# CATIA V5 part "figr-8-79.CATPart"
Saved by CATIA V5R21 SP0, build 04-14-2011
Part number: Part1
Bounding box of the stored display mesh (mm): x -35 to 35, y -116.369 to 116.369, z 0 to 117.647
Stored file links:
  D:\CATIA V5R21 E-RESOURCES\CATIA-V5R21\catia-v5r21-prt\c08-catia-v5r20-prt\c08-catia-v5r21-figr-8-79.CATPart
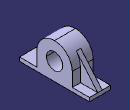
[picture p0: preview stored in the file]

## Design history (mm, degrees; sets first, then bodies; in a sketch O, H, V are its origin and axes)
Body1 (main body)
  Sketch1 on yz-plane, origin (0, 0, 0), H (0, 1, 0), V (0, 0, 1)
    line L1 (0, 0) -> (116.3687, 0)
    point P1 (116.3687, 0)
    line L2 (116.3687, 0) -> (116.3687, 12.5279)
    point P2 (116.3687, 12.5279)
    line L3 (116.3687, 12.5279) -> (58.943, 12.5279)
    point P3 (58.943, 12.5279)
    line L4 (58.943, 12.5279) -> (58.943, 58.7038)
    point P4 (58.943, 58.7038)
    arc A1 centre (0, 58.7038) radius 58.943 from (58.943, 58.7038) to (0, 117.6467) ccw
    point P5 (0, 58.7038)
    point P6 (-58.943, 58.7038)
    line L5 (-58.943, 58.7038) -> (-58.943, 12.5279)
    point P7 (-58.943, 12.5279)
    axis line L6 (0, 0) -> (0, 108.1111)
    point P9 (0, 117.6467)
    point P10 (0, 117.6467)
    point P11 (-58.943, 58.7038)
    arc A2 centre (0, 58.7038) radius 58.943 from (-58.943, 58.7038) to (0, 117.6467) cw
    point P13 (-58.943, 12.5279)
    point P14 (-116.3687, 12.5279)
    line L7 (-116.3687, 12.5279) -> (-58.943, 12.5279)
    point P15 (-116.3687, 0)
    line L8 (-116.3687, 0) -> (-116.3687, 12.5279)
    point P16 (0, 0)
    line L9 (0, 0) -> (-116.3687, 0)
    circle A3 centre (0, 58.7038) radius 27.1825
    horizontal: L1 H, L3 H
    vertical: L2 V, L4 V, L6 V
    tangency: A1 L4, L5 A1
    coincidence: P7 L3, P5 V, L6 P9, P6 P11, O P16, P9 P10, P7 P13
    symmetry: P9 P10 L6, P4 P11 L6, A1 A2 L6, P3 P13 L6, P2 P14 L6, L3 L7 L6, P1 P15 L6, L2 L8 L6, O P16 L6, L1 L9 L6
  Pad1: profile Sketch1, direction (1, 0, 0), length 35, mirrored extent
  Sketch2 on yz-plane, origin (0, 0, 0), H (0, 1, 0), V (0, 0, 1)
    line L1 (116.3687, 12.5279) -> (44.9741, 96.8037)
    point P1 (116.3687, 12.5279)
    point P2 (44.9741, 96.8037)
    reference projected arc E1 centre (0, 58.7038) radius 58.943 from (58.943, 58.7038) to (0, 117.6467) ccw from edge [face of Pad1 | face of Pad1]
    reference projected arc E2 centre (0, 58.7038) radius 58.943 from (58.943, 58.7038) to (0, 117.6467) ccw from edge [face of Pad1 | face of Pad1]
    reference projected point E3 (116.3687, 12.5279) from vertex [face of Pad1 | face of Pad1 | face of Pad1]
    tangency: L1 E1
    coincidence: P2 E2, P1 E3
  Stiffener1: ExtendedProfile Sketch2, ThicknessTop 0, ThicknessValue 15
